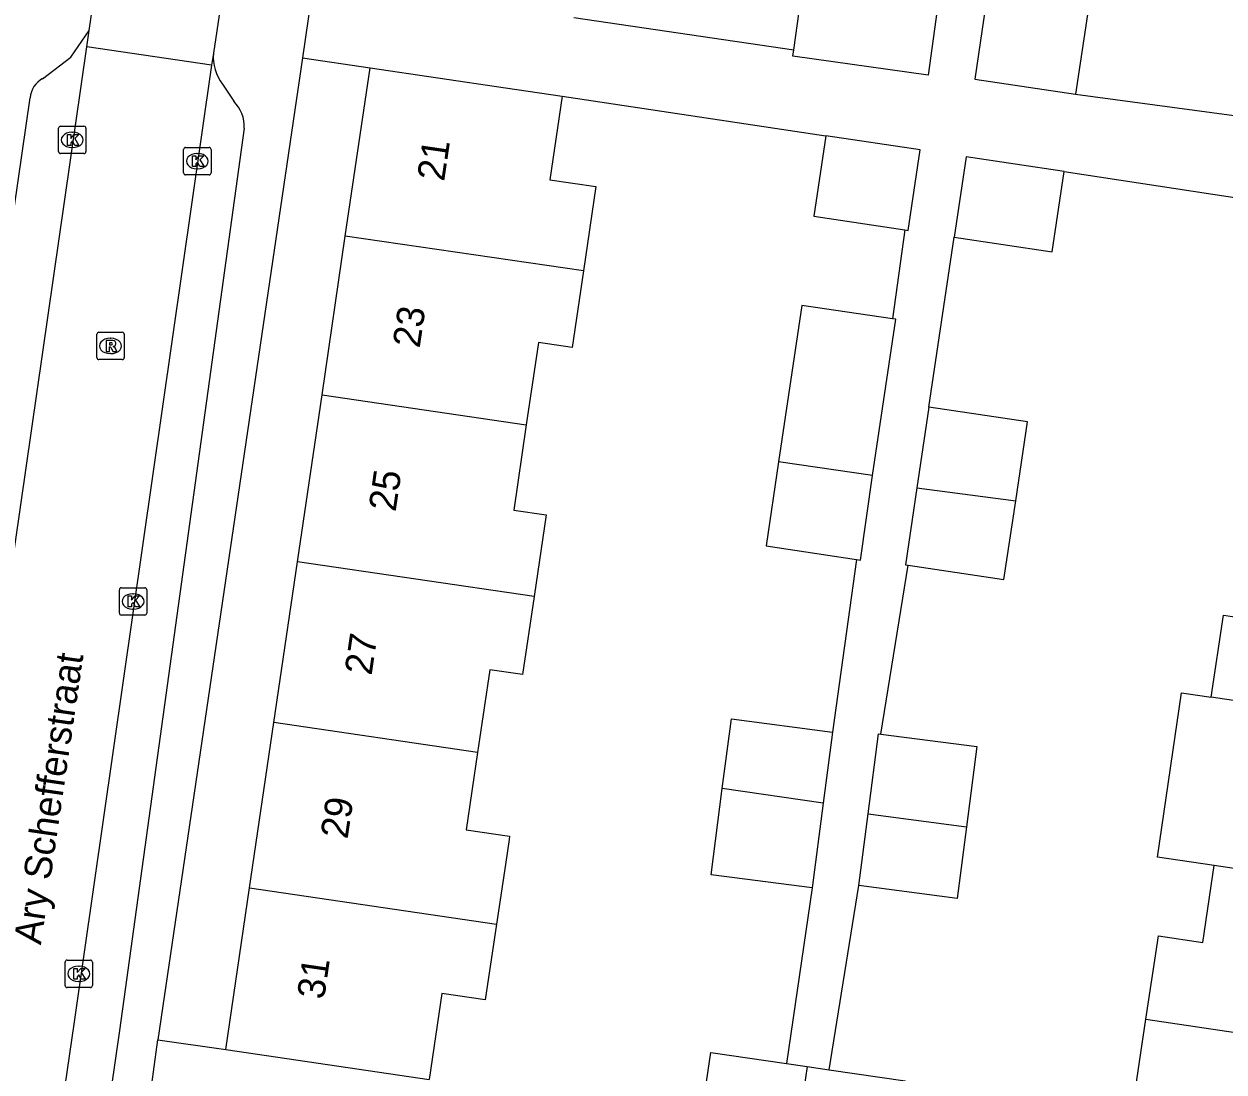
# Model space of a CAD drawing. Extents: x 163686 to 164493, y 382719 to 383870.
# Drawn here: x 164031.02 to 164074.82, y 382940.91 to 382979.16 of the extents above; entities that cross this region are included whole.
import ezdxf

# ---------------------------------------------------------------- set-up
doc = ezdxf.new("R2010")
doc.units = 0
for name, color, linetype in [('IMGEO_Groenvoorziening', 7, 'Continuous'), ('IMGEO_Kolk', 7, 'Continuous'), ('IMGEO_Openbare_ruimte_label', 7, 'Continuous'), ('IMGEO_Pand', 7, 'Continuous'), ('IMGEO_Pand_nummerreeks', 7, 'Continuous'), ('IMGEO_Rijbaan_lokaal_open', 7, 'Continuous'), ('IMGEO_Rioolput', 7, 'Continuous'), ('IMGEO_Voetpad_open', 7, 'Continuous')]:
    doc.layers.add(name, color=color, linetype=linetype)

msp = doc.modelspace()

# ---------------------------------------------------------------- linework, layer by layer
at = {"layer": 'IMGEO_Groenvoorziening'}
msp.add_lwpolyline([(164035.904, 382942.087), (164038.39, 382941.729)], dxfattribs=at)
at = {"layer": 'IMGEO_Kolk'}
for p, q in [((164032.284, 382974.504), (164032.284, 382975.356)), ((164032.359, 382975.43), (164033.211, 382975.43)), ((164032.772, 382975.21), (164032.797, 382975.21)), ((164033.285, 382975.356), (164033.285, 382974.504)), ((164032.795, 382974.65), (164032.77, 382974.65)), ((164036.923, 382974.654), (164037.775, 382974.654)), ((164033.211, 382974.43), (164032.359, 382974.43)), ((164036.848, 382973.728), (164036.848, 382974.58)), ((164037.336, 382974.434), (164037.361, 382974.434)), ((164037.849, 382974.58), (164037.849, 382973.728)), ((164037.359, 382973.874), (164037.334, 382973.874)), ((164037.775, 382973.654), (164036.923, 382973.654)), ((164034.503, 382957.66), (164034.503, 382958.512)), ((164034.578, 382958.586), (164035.43, 382958.586)), ((164035.504, 382958.512), (164035.504, 382957.66)), ((164034.991, 382958.366), (164035.016, 382958.366)), ((164035.43, 382957.586), (164034.578, 382957.586)), ((164035.014, 382957.806), (164034.989, 382957.806)), ((164032.522, 382944.069), (164032.522, 382944.921)), ((164032.597, 382944.995), (164033.449, 382944.995)), ((164033.523, 382944.921), (164033.523, 382944.069)), ((164033.01, 382944.775), (164033.035, 382944.775)), ((164033.449, 382943.995), (164032.597, 382943.995)), ((164033.033, 382944.215), (164033.008, 382944.215))]:
    msp.add_line(p, q, dxfattribs=at)
for points in [[(164032.284, 382974.504), (164032.284, 382975.356)], [(164032.359, 382975.43), (164033.211, 382975.43)], [(164032.605, 382975.13), (164032.728, 382975.13), (164032.728, 382974.979), (164032.858, 382975.13), (164033.022, 382975.13), (164032.876, 382974.979), (164033.029, 382974.73), (164032.877, 382974.73), (164032.792, 382974.894), (164032.728, 382974.827), (164032.728, 382974.73), (164032.605, 382974.73), (164032.605, 382975.13)], [(164033.285, 382975.356), (164033.285, 382974.504)], [(164036.923, 382974.654), (164037.775, 382974.654)], [(164033.211, 382974.43), (164032.359, 382974.43)], [(164036.848, 382973.728), (164036.848, 382974.58)], [(164037.169, 382974.354), (164037.292, 382974.354), (164037.292, 382974.203), (164037.422, 382974.354), (164037.586, 382974.354), (164037.44, 382974.203), (164037.593, 382973.954), (164037.441, 382973.954), (164037.356, 382974.118), (164037.292, 382974.051), (164037.292, 382973.954), (164037.169, 382973.954), (164037.169, 382974.354)], [(164037.849, 382974.58), (164037.849, 382973.728)], [(164037.775, 382973.654), (164036.923, 382973.654)], [(164034.503, 382957.66), (164034.503, 382958.512)], [(164034.578, 382958.586), (164035.43, 382958.586)], [(164035.504, 382958.512), (164035.504, 382957.66)], [(164034.824, 382958.286), (164034.947, 382958.286), (164034.947, 382958.135), (164035.077, 382958.286), (164035.241, 382958.286), (164035.095, 382958.135), (164035.248, 382957.886), (164035.096, 382957.886), (164035.011, 382958.05), (164034.947, 382957.983), (164034.947, 382957.886), (164034.824, 382957.886), (164034.824, 382958.286)], [(164035.43, 382957.586), (164034.578, 382957.586)], [(164032.522, 382944.069), (164032.522, 382944.921)], [(164032.597, 382944.995), (164033.449, 382944.995)], [(164033.523, 382944.921), (164033.523, 382944.069)], [(164032.843, 382944.695), (164032.966, 382944.695), (164032.966, 382944.544), (164033.096, 382944.695), (164033.26, 382944.695), (164033.114, 382944.544), (164033.267, 382944.295), (164033.115, 382944.295), (164033.03, 382944.459), (164032.966, 382944.392), (164032.966, 382944.295), (164032.843, 382944.295), (164032.843, 382944.695)], [(164033.449, 382943.995), (164032.597, 382943.995)]]:
    msp.add_lwpolyline(points, dxfattribs=at)
for centre, start, end in [((164032.361, 382975.354), 91.552, 178.448), ((164032.361, 382975.354), 91.552, 178.448), ((164033.209, 382975.354), 1.552, 88.448), ((164033.209, 382975.354), 1.552, 88.448), ((164036.925, 382974.578), 91.552, 178.448), ((164036.925, 382974.578), 91.552, 178.448), ((164037.773, 382974.578), 1.552, 88.448), ((164037.773, 382974.578), 1.552, 88.448), ((164032.361, 382974.506), 181.552, 268.448), ((164032.361, 382974.506), 181.552, 268.448), ((164033.209, 382974.506), 271.552, 358.448), ((164033.209, 382974.506), 271.552, 358.448), ((164036.925, 382973.73), 181.552, 268.448), ((164036.925, 382973.73), 181.552, 268.448), ((164037.773, 382973.73), 271.552, 358.448), ((164037.773, 382973.73), 271.552, 358.448), ((164034.58, 382958.51), 91.552, 178.448), ((164034.58, 382958.51), 91.552, 178.448), ((164035.428, 382958.51), 1.552, 88.448), ((164035.428, 382958.51), 1.552, 88.448), ((164034.58, 382957.662), 181.552, 268.448), ((164034.58, 382957.662), 181.552, 268.448), ((164035.428, 382957.662), 271.552, 358.448), ((164035.428, 382957.662), 271.552, 358.448), ((164032.599, 382944.919), 91.552, 178.448), ((164032.599, 382944.919), 91.552, 178.448), ((164033.447, 382944.919), 1.552, 88.448), ((164033.447, 382944.919), 1.552, 88.448), ((164032.599, 382944.071), 181.552, 268.448), ((164032.599, 382944.071), 181.552, 268.448), ((164033.447, 382944.071), 271.552, 358.448), ((164033.447, 382944.071), 271.552, 358.448)]:
    msp.add_arc(centre, 0.0765, start, end, dxfattribs=at)
for centre, major_axis, ratio, start_param, end_param in [((164032.771, 382974.93), (-0.387, 0.002), 0.722429, 4.712389, 7.853982), ((164032.796, 382974.93), (-0.39, 0.002), 0.717154, 1.570796, 4.712389), ((164037.335, 382974.154), (-0.387, 0.002), 0.722429, 4.712389, 7.853982), ((164037.36, 382974.154), (-0.39, 0.002), 0.717154, 1.570796, 4.712389), ((164034.99, 382958.086), (-0.387, 0.002), 0.722429, 4.712389, 7.853982), ((164035.015, 382958.086), (-0.39, 0.002), 0.717154, 1.570796, 4.712389), ((164033.009, 382944.495), (-0.387, 0.002), 0.722429, 4.712389, 7.853982), ((164033.034, 382944.495), (-0.39, 0.002), 0.717154, 1.570796, 4.712389)]:
    msp.add_ellipse(centre, major_axis=major_axis, ratio=ratio, start_param=start_param, end_param=end_param, dxfattribs=at)
at = {"layer": 'IMGEO_Pand'}
for points in [[(164059.116, 382978.212), (164059.956, 382984.268), (164064.889, 382983.583)], [(164064.889, 382983.583), (164064.017, 382977.297), (164059.084, 382977.981), (164059.116, 382978.212)], [(164066.302, 382980.287), (164066.188, 382980.304), (164065.718, 382977.151), (164069.402, 382976.601)], [(164069.873, 382979.755), (164069.402, 382976.601)], [(164042.75, 382971.422), (164043.651, 382977.56)], [(164043.651, 382977.56), (164048.598, 382976.833), (164050.662, 382976.53)], [(164050.662, 382976.53), (164050.213, 382973.478), (164051.893, 382973.232), (164051.44, 382970.146)], [(164060.286, 382975.075), (164059.85, 382972.141), (164063.171, 382971.647)], [(164063.171, 382971.647), (164063.289, 382971.629), (164063.726, 382974.562), (164060.286, 382975.075)], [(164068.983, 382973.779), (164065.412, 382974.311), (164064.975, 382971.378)], [(164064.975, 382971.378), (164068.545, 382970.846), (164068.983, 382973.779)], [(164041.899, 382965.627), (164042.75, 382971.422)], [(164051.44, 382970.146), (164042.75, 382971.422)], [(164051.44, 382970.146), (164051.029, 382967.349), (164049.795, 382967.53), (164049.355, 382964.532)], [(164062.72, 382968.399), (164059.411, 382968.892), (164058.56, 382963.18)], [(164061.986, 382962.677), (164062.836, 382968.382), (164062.72, 382968.399)], [(164041.004, 382959.529), (164041.899, 382965.627)], [(164041.899, 382965.627), (164049.355, 382964.532)], [(164064.051, 382965.173), (164063.613, 382962.231)], [(164067.216, 382961.763), (164067.644, 382964.637), (164064.051, 382965.173)], [(164049.355, 382964.532), (164048.897, 382961.415), (164050.074, 382961.243), (164049.636, 382958.261)], [(164058.56, 382963.18), (164058.103, 382960.111), (164061.403, 382959.62)], [(164061.986, 382962.677), (164058.56, 382963.18)], [(164061.403, 382959.62), (164061.549, 382959.598), (164061.986, 382962.677)], [(164063.613, 382962.231), (164063.194, 382959.423), (164063.295, 382959.408)], [(164063.613, 382962.231), (164067.216, 382961.763)], [(164063.295, 382959.408), (164066.787, 382958.888), (164067.216, 382961.763)], [(164074.35, 382954.589), (164074.796, 382957.58), (164075.783, 382957.433), (164076.242, 382960.509)], [(164040.142, 382953.663), (164041.004, 382959.529)], [(164049.636, 382958.261), (164041.004, 382959.529)], [(164049.636, 382958.261), (164049.218, 382955.416), (164048.019, 382955.592), (164047.611, 382952.812), (164047.576, 382952.571)], [(164074.459, 382948.447), (164072.389, 382948.755), (164073.27, 382954.75), (164074.35, 382954.589)], [(164082.735, 382953.339), (164074.35, 382954.589)], [(164039.257, 382947.636), (164040.142, 382953.663)], [(164047.576, 382952.571), (164040.142, 382953.663)], [(164056.508, 382951.259), (164056.838, 382953.797), (164060.531, 382953.317)], [(164060.531, 382953.317), (164060.193, 382950.718)], [(164061.826, 382950.33), (164062.206, 382953.256), (164062.297, 382953.244)], [(164062.297, 382953.244), (164065.795, 382952.79), (164065.415, 382949.864)], [(164047.576, 382952.571), (164047.162, 382949.755), (164048.746, 382949.523), (164048.727, 382949.393), (164048.593, 382948.491), (164048.268, 382946.312)], [(164059.792, 382947.634), (164056.099, 382948.114), (164056.508, 382951.259)], [(164060.193, 382950.718), (164056.508, 382951.259)], [(164060.193, 382950.718), (164059.792, 382947.634)], [(164061.486, 382947.714), (164061.826, 382950.33)], [(164061.826, 382950.33), (164065.415, 382949.864)], [(164065.415, 382949.864), (164065.075, 382947.248), (164061.486, 382947.714)], [(164071.969, 382942.844), (164072.291, 382945), (164072.423, 382945.887), (164074.041, 382945.645), (164074.459, 382948.447)], [(164081.841, 382947.347), (164074.459, 382948.447)], [(164038.39, 382941.729), (164039.257, 382947.636)], [(164039.257, 382947.636), (164048.268, 382946.312)], [(164048.268, 382946.312), (164047.855, 382943.545), (164046.272, 382943.777), (164045.811, 382940.639)], [(164072.668, 382936.681), (164073.136, 382939.818), (164071.553, 382940.054), (164071.969, 382942.844)], [(164071.969, 382942.844), (164080.969, 382941.503)], [(164038.39, 382941.729), (164045.811, 382940.639)], [(164055.729, 382939.152), (164056.092, 382941.626), (164058.851, 382941.221)], [(164058.851, 382941.221), (164059.609, 382941.11)], [(164059.609, 382941.11), (164059.243, 382938.636)], [(164059.609, 382941.11), (164060.404, 382940.993)], [(164060.404, 382940.993), (164063.187, 382940.585), (164062.824, 382938.111)]]:
    msp.add_lwpolyline(points, dxfattribs=at)
at = {"layer": 'IMGEO_Rijbaan_lokaal_open'}
for points in [[(164033.399, 382978.926), (164033.886, 382982.27)], [(164038.458, 382981.607), (164037.934, 382978.093)], [(164033.312, 382978.332), (164033.399, 382978.926)], [(164026.328, 382931.232), (164028.267, 382943.381), (164033.312, 382978.332)], [(164037.869, 382977.652), (164033.312, 382978.332)], [(164037.934, 382978.093), (164037.869, 382977.652)], [(164037.869, 382977.652), (164032.837, 382942.654), (164031.035, 382930.239)]]:
    msp.add_lwpolyline(points, dxfattribs=at)
at = {"layer": 'IMGEO_Rioolput'}
for p, q in [((164033.681, 382966.984), (164033.681, 382967.836)), ((164033.756, 382967.91), (164034.608, 382967.91)), ((164034.169, 382967.69), (164034.194, 382967.69)), ((164034.682, 382967.836), (164034.682, 382966.984)), ((164034.608, 382966.91), (164033.756, 382966.91)), ((164034.192, 382967.13), (164034.167, 382967.13))]:
    msp.add_line(p, q, dxfattribs=at)
for points in [[(164033.681, 382966.984), (164033.681, 382967.836)], [(164033.756, 382967.91), (164034.608, 382967.91)], [(164034.27, 382967.608), (164034.018, 382967.61), (164034.018, 382967.21)], [(164034.682, 382967.836), (164034.682, 382966.984)], [(164034.018, 382967.21), (164034.142, 382967.21), (164034.142, 382967.372), (164034.153, 382967.372)], [(164034.196, 382967.529), (164034.142, 382967.529), (164034.142, 382967.448)], [(164034.142, 382967.448), (164034.194, 382967.448)], [(164034.2, 382967.343), (164034.271, 382967.21), (164034.411, 382967.21), (164034.346, 382967.336)], [(164034.608, 382966.91), (164033.756, 382966.91)]]:
    msp.add_lwpolyline(points, dxfattribs=at)
for centre, radius, start, end in [((164033.758, 382967.834), 0.0765, 91.552, 178.448), ((164033.758, 382967.834), 0.0765, 91.552, 178.448), ((164034.269, 382967.498), 0.109, 350.3612, 89.416), ((164034.606, 382967.834), 0.0765, 1.552, 88.448), ((164034.606, 382967.834), 0.0765, 1.552, 88.448), ((164034.152, 382967.319), 0.0533, 26.0293, 88.6989), ((164034.178, 382967.637), 0.19, 274.7715, 282.9687), ((164034.202, 382967.433), 0.0964, 77.0061, 93.1865), ((164034.216, 382967.49), 0.0378, 276.6634, 79.6772), ((164034.267, 382967.498), 0.112, 277.5842, 350.9817), ((164034.251, 382967.283), 0.108, 29.5134, 73.7905), ((164033.758, 382966.986), 0.0765, 181.552, 268.448), ((164033.758, 382966.986), 0.0765, 181.552, 268.448), ((164034.606, 382966.986), 0.0765, 271.552, 358.448), ((164034.606, 382966.986), 0.0765, 271.552, 358.448)]:
    msp.add_arc(centre, radius, start, end, dxfattribs=at)
for centre, major_axis, ratio, start_param, end_param in [((164034.168, 382967.41), (-0.387, 0.002), 0.722429, 4.712389, 7.853982), ((164034.193, 382967.41), (-0.39, 0.002), 0.717154, 1.570796, 4.712389)]:
    msp.add_ellipse(centre, major_axis=major_axis, ratio=ratio, start_param=start_param, end_param=end_param, dxfattribs=at)
at = {"layer": 'IMGEO_Voetpad_open'}
for points in [[(164041.604, 382980.786), (164041.182, 382977.924)], [(164051.084, 382979.393), (164059.116, 382978.212)], [(164031.704, 382977.164), (164032.73, 382977.955), (164033.399, 382978.926)], [(164041.182, 382977.924), (164035.904, 382942.087)], [(164041.182, 382977.924), (164043.651, 382977.56)], [(164038.27, 382976.959), (164038.678, 382976.338)], [(164025.123, 382933.834), (164026.518, 382943.815), (164031.25, 382976.464)], [(164050.662, 382976.53), (164060.286, 382975.075)], [(164069.402, 382976.601), (164075.823, 382975.736)], [(164039.063, 382975.361), (164034.507, 382942.427), (164033.1, 382932.664)], [(164068.983, 382973.779), (164078.402, 382972.341)], [(164063.171, 382971.647), (164062.72, 382968.399)], [(164064.051, 382965.173), (164064.975, 382971.378)], [(164061.403, 382959.62), (164060.531, 382953.317)], [(164062.297, 382953.244), (164063.295, 382959.408)], [(164059.792, 382947.634), (164058.851, 382941.221)], [(164060.404, 382940.993), (164061.486, 382947.714)], [(164035.122, 382936.251), (164035.904, 382942.087)]]:
    msp.add_lwpolyline(points, dxfattribs=at)
for centre, radius, start, end in [((164039.709, 382978.002), 1.778, 177.0746, 215.9341), ((164032.105, 382976.407), 0.857, 117.8881, 176.1793), ((164037.768, 382975.415), 1.296, 357.6044, 45.4108)]:
    msp.add_arc(centre, radius, start, end, dxfattribs=at)

# ---------------------------------------------------------------- texts
at = {"layer": 'IMGEO_Openbare_ruimte_label'}
msp.add_text('Ary Schefferstraat', height=1, rotation=81.6591, dxfattribs=at).set_placement((164031.639, 382945.534))
at = {"layer": 'IMGEO_Pand_nummerreeks'}
for s, rotation, p in [('21', 81.647, (164046.355, 382973.392)), ('23', 81.647, (164045.461, 382967.308)), ('25', 81.647, (164044.584, 382961.336)), ('27', 81.6465, (164043.707, 382955.364)), ('29', 81.6465, (164042.83, 382949.392)), ('31', 81.647, (164041.971, 382943.533))]:
    msp.add_text(s, height=1, rotation=rotation, dxfattribs=at).set_placement(p)

doc.saveas('drawing.dxf')
